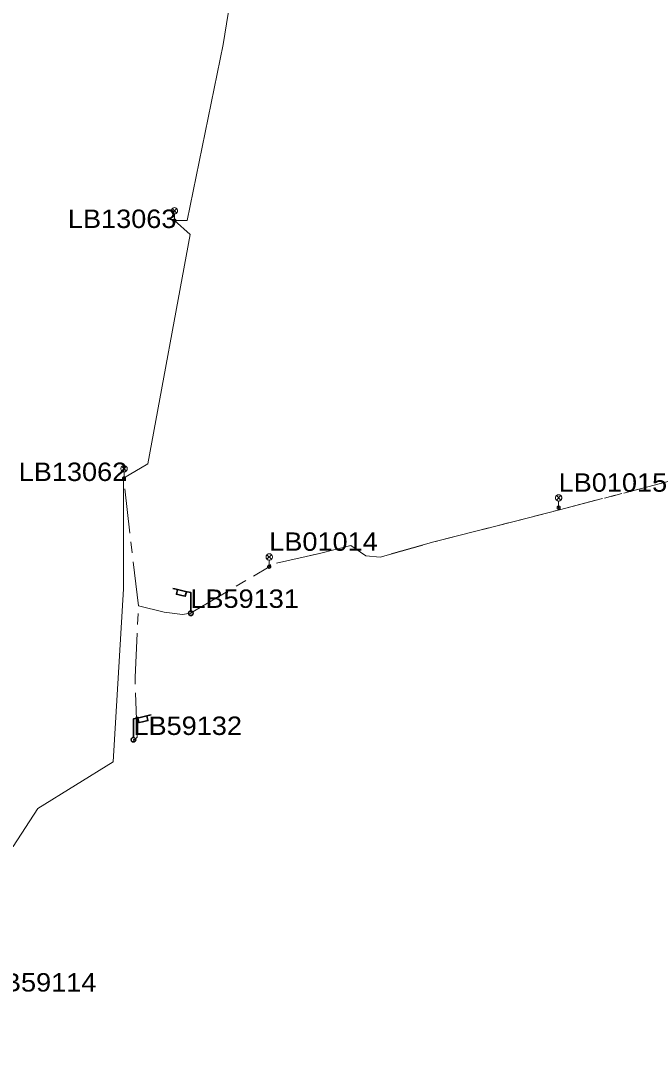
# Model space of a CAD drawing. Extents: x -688049 to -687261, y -973611 to -973038.
# Drawn here: x -687593.4 to -687519.3, y -973304.1 to -973181.4 of the extents above; entities that cross this region are included whole.
import ezdxf

# ---------------------------------------------------------------- set-up
doc = ezdxf.new("R2010")
doc.units = 0
doc.header["$LTSCALE"] = 0.87
doc.linetypes.add('LONG_DASH_SHORT_DASH', pattern=[9.9, 6, -1.2, 1.5, -1.2])
doc.layers.add('1', color=7, linetype='Continuous', lineweight=13)

msp = doc.modelspace()

# ---------------------------------------------------------------- linework, layer by layer
at = {"layer": '1'}
for p, q in [((-687575.645, -973203.485), (-687575.115, -973204.015)), ((-687575.645, -973204.015), (-687575.115, -973203.485)), ((-687575.38, -973204.9), (-687575.38, -973204.125)), ((-687581.575, -973233.825), (-687581.045, -973234.355)), ((-687581.575, -973234.355), (-687581.045, -973233.825)), ((-687581.31, -973235.24), (-687581.31, -973234.465)), ((-687530.455, -973237.255), (-687529.925, -973237.785)), ((-687530.455, -973237.785), (-687529.925, -973237.255)), ((-687530.19, -973238.67), (-687530.19, -973237.895)), ((-687564.495, -973244.205), (-687563.965, -973244.735)), ((-687564.495, -973244.735), (-687563.965, -973244.205)), ((-687564.23, -973245.62), (-687564.23, -973244.845))]:
    msp.add_line(p, q, dxfattribs=at)
at = {"layer": '1', "linetype": 'LONG_DASH_SHORT_DASH'}
for p, q in [((-687579.62, -973250.21), (-687581.366, -973235.196)), ((-687579.62, -973250.21), (-687581.366, -973235.196)), ((-687579.62, -973250.21), (-687581.366, -973235.196)), ((-687579.62, -973250.21), (-687581.366, -973235.196)), ((-687579.62, -973250.21), (-687581.366, -973235.196)), ((-687579.62, -973250.21), (-687581.366, -973235.196)), ((-687579.62, -973250.21), (-687581.366, -973235.196)), ((-687530.07, -973238.91), (-687520.8, -973236.51)), ((-687530.07, -973238.91), (-687520.8, -973236.51)), ((-687530.07, -973238.91), (-687520.8, -973236.51)), ((-687530.07, -973238.91), (-687520.8, -973236.51)), ((-687539.11, -973241.23), (-687530.07, -973238.91)), ((-687539.11, -973241.23), (-687530.07, -973238.91)), ((-687539.11, -973241.23), (-687530.07, -973238.91)), ((-687530.07, -973238.91), (-687530.19, -973238.67)), ((-687530.07, -973238.91), (-687530.19, -973238.67)), ((-687530.07, -973238.91), (-687530.19, -973238.67)), ((-687573.51, -973251.1), (-687564.23, -973245.62)), ((-687573.51, -973251.1), (-687564.23, -973245.62)), ((-687573.51, -973251.1), (-687564.23, -973245.62)), ((-687573.51, -973251.1), (-687564.23, -973245.62)), ((-687573.51, -973251.1), (-687564.23, -973245.62)), ((-687573.51, -973251.1), (-687564.23, -973245.62)), ((-687573.51, -973251.1), (-687564.23, -973245.62)), ((-687580.01, -973258.67), (-687579.62, -973250.21)), ((-687580.01, -973258.67), (-687579.62, -973250.21)), ((-687580.01, -973258.67), (-687579.62, -973250.21)), ((-687580.01, -973258.67), (-687579.62, -973250.21)), ((-687580.01, -973258.67), (-687579.62, -973250.21)), ((-687580.01, -973258.67), (-687579.62, -973250.21)), ((-687579.62, -973250.21), (-687576.58, -973250.95)), ((-687579.62, -973250.21), (-687576.58, -973250.95)), ((-687579.62, -973250.21), (-687576.58, -973250.95)), ((-687579.62, -973250.21), (-687576.58, -973250.95)), ((-687579.62, -973250.21), (-687576.58, -973250.95)), ((-687579.62, -973250.21), (-687576.58, -973250.95)), ((-687579.62, -973250.21), (-687576.58, -973250.95)), ((-687576.58, -973250.95), (-687574.42, -973251.25)), ((-687576.58, -973250.95), (-687574.42, -973251.25)), ((-687576.58, -973250.95), (-687574.42, -973251.25)), ((-687576.58, -973250.95), (-687574.42, -973251.25)), ((-687576.58, -973250.95), (-687574.42, -973251.25)), ((-687576.58, -973250.95), (-687574.42, -973251.25)), ((-687574.42, -973251.25), (-687573.51, -973251.1)), ((-687574.42, -973251.25), (-687573.51, -973251.1)), ((-687574.42, -973251.25), (-687573.51, -973251.1)), ((-687574.42, -973251.25), (-687573.51, -973251.1)), ((-687574.42, -973251.25), (-687573.51, -973251.1)), ((-687574.42, -973251.25), (-687573.51, -973251.1)), ((-687579.78, -973265.69), (-687580.01, -973258.67)), ((-687579.78, -973265.69), (-687580.01, -973258.67)), ((-687579.78, -973265.69), (-687580.01, -973258.67)), ((-687579.78, -973265.69), (-687580.01, -973258.67)), ((-687580.2, -973266.05), (-687579.78, -973265.69)), ((-687580.2, -973266.05), (-687579.78, -973265.69)), ((-687580.2, -973266.05), (-687579.78, -973265.69)), ((-687580.2, -973266.05), (-687579.78, -973265.69)), ((-687580.2, -973266.05), (-687579.78, -973265.69)), ((-687580.2, -973266.05), (-687579.78, -973265.69))]:
    msp.add_line(p, q, dxfattribs=at)
at = {"layer": '1', "lineweight": 35}
for p, q in [((-687573.425, -973251.1), (-687573.479, -973251.1)), ((-687580.243, -973265.968), (-687580.189, -973265.968))]:
    msp.add_line(p, q, dxfattribs=at)
at = {"layer": '1'}
for points in [[(-687575.38, -973204.9), (-687573.874, -973204.9), (-687569.663, -973184.163), (-687567.048, -973168.085), (-687568.06, -973166.7)], [(-687581.366, -973235.196), (-687578.492, -973233.52), (-687573.548, -973206.552), (-687575.38, -973204.9)], [(-687581.366, -973235.196), (-687581.366, -973248.239), (-687582.584, -973268.559), (-687591.459, -973274.079), (-687594.36, -973278.544), (-687605.262, -973276.884), (-687608.072, -973288.54), (-687610.025, -973292.76), (-687612.471, -973294.66), (-687613.949, -973301.72), (-687622.891, -973301.881), (-687623.316, -973303.267), (-687623.86, -973304.14)]]:
    msp.add_lwpolyline(points, dxfattribs=at)
for points in [[(-687575.005, -973203.75), (-687575.011, -973203.685), (-687575.028, -973203.622), (-687575.055, -973203.562), (-687575.093, -973203.509), (-687575.139, -973203.463), (-687575.192, -973203.425), (-687575.252, -973203.398), (-687575.315, -973203.381), (-687575.38, -973203.375), (-687575.445, -973203.381), (-687575.508, -973203.398), (-687575.568, -973203.425), (-687575.621, -973203.463), (-687575.667, -973203.509), (-687575.705, -973203.562), (-687575.732, -973203.622), (-687575.749, -973203.685), (-687575.755, -973203.75), (-687575.749, -973203.815), (-687575.732, -973203.878), (-687575.705, -973203.938), (-687575.667, -973203.991), (-687575.621, -973204.037), (-687575.568, -973204.075), (-687575.508, -973204.102), (-687575.445, -973204.119), (-687575.38, -973204.125), (-687575.315, -973204.119), (-687575.252, -973204.102), (-687575.192, -973204.075), (-687575.139, -973204.037), (-687575.093, -973203.991), (-687575.055, -973203.938), (-687575.028, -973203.878), (-687575.011, -973203.815)], [(-687575.19, -973204.9), (-687575.193, -973204.867), (-687575.201, -973204.835), (-687575.215, -973204.805), (-687575.234, -973204.778), (-687575.258, -973204.754), (-687575.285, -973204.735), (-687575.315, -973204.721), (-687575.347, -973204.713), (-687575.38, -973204.71), (-687575.413, -973204.713), (-687575.445, -973204.721), (-687575.475, -973204.735), (-687575.502, -973204.754), (-687575.526, -973204.778), (-687575.545, -973204.805), (-687575.559, -973204.835), (-687575.567, -973204.867), (-687575.57, -973204.9), (-687575.567, -973204.933), (-687575.559, -973204.965), (-687575.545, -973204.995), (-687575.526, -973205.022), (-687575.502, -973205.046), (-687575.475, -973205.065), (-687575.445, -973205.079), (-687575.413, -973205.087), (-687575.38, -973205.09), (-687575.347, -973205.087), (-687575.315, -973205.079), (-687575.285, -973205.065), (-687575.258, -973205.046), (-687575.234, -973205.022), (-687575.215, -973204.995), (-687575.201, -973204.965), (-687575.193, -973204.933)], [(-687575.33, -973204.9), (-687575.331, -973204.891), (-687575.333, -973204.883), (-687575.337, -973204.875), (-687575.342, -973204.868), (-687575.348, -973204.862), (-687575.355, -973204.857), (-687575.363, -973204.853), (-687575.371, -973204.851), (-687575.38, -973204.85), (-687575.389, -973204.851), (-687575.397, -973204.853), (-687575.405, -973204.857), (-687575.412, -973204.862), (-687575.418, -973204.868), (-687575.423, -973204.875), (-687575.427, -973204.883), (-687575.429, -973204.891), (-687575.43, -973204.9), (-687575.429, -973204.909), (-687575.427, -973204.917), (-687575.423, -973204.925), (-687575.418, -973204.932), (-687575.412, -973204.938), (-687575.405, -973204.943), (-687575.397, -973204.947), (-687575.389, -973204.949), (-687575.38, -973204.95), (-687575.371, -973204.949), (-687575.363, -973204.947), (-687575.355, -973204.943), (-687575.348, -973204.938), (-687575.342, -973204.932), (-687575.337, -973204.925), (-687575.333, -973204.917), (-687575.331, -973204.909)], [(-687580.935, -973234.09), (-687580.941, -973234.025), (-687580.958, -973233.962), (-687580.985, -973233.903), (-687581.023, -973233.849), (-687581.069, -973233.803), (-687581.122, -973233.765), (-687581.182, -973233.738), (-687581.245, -973233.721), (-687581.31, -973233.715), (-687581.375, -973233.721), (-687581.438, -973233.738), (-687581.498, -973233.765), (-687581.551, -973233.803), (-687581.597, -973233.849), (-687581.635, -973233.903), (-687581.662, -973233.962), (-687581.679, -973234.025), (-687581.685, -973234.09), (-687581.679, -973234.155), (-687581.662, -973234.218), (-687581.635, -973234.278), (-687581.597, -973234.331), (-687581.551, -973234.377), (-687581.498, -973234.415), (-687581.438, -973234.442), (-687581.375, -973234.459), (-687581.31, -973234.465), (-687581.245, -973234.459), (-687581.182, -973234.442), (-687581.122, -973234.415), (-687581.069, -973234.377), (-687581.023, -973234.331), (-687580.985, -973234.278), (-687580.958, -973234.218), (-687580.941, -973234.155)], [(-687581.12, -973235.24), (-687581.123, -973235.207), (-687581.131, -973235.175), (-687581.145, -973235.145), (-687581.164, -973235.118), (-687581.188, -973235.094), (-687581.215, -973235.075), (-687581.245, -973235.061), (-687581.277, -973235.053), (-687581.31, -973235.05), (-687581.343, -973235.053), (-687581.375, -973235.061), (-687581.405, -973235.075), (-687581.432, -973235.094), (-687581.456, -973235.118), (-687581.475, -973235.145), (-687581.489, -973235.175), (-687581.497, -973235.207), (-687581.5, -973235.24), (-687581.497, -973235.273), (-687581.489, -973235.305), (-687581.475, -973235.335), (-687581.456, -973235.362), (-687581.432, -973235.386), (-687581.405, -973235.405), (-687581.375, -973235.419), (-687581.343, -973235.427), (-687581.31, -973235.43), (-687581.277, -973235.427), (-687581.245, -973235.419), (-687581.215, -973235.405), (-687581.188, -973235.386), (-687581.164, -973235.362), (-687581.145, -973235.335), (-687581.131, -973235.305), (-687581.123, -973235.273)], [(-687581.26, -973235.24), (-687581.261, -973235.231), (-687581.263, -973235.223), (-687581.267, -973235.215), (-687581.272, -973235.208), (-687581.278, -973235.202), (-687581.285, -973235.197), (-687581.293, -973235.193), (-687581.301, -973235.191), (-687581.31, -973235.19), (-687581.319, -973235.191), (-687581.327, -973235.193), (-687581.335, -973235.197), (-687581.342, -973235.202), (-687581.348, -973235.208), (-687581.353, -973235.215), (-687581.357, -973235.223), (-687581.359, -973235.231), (-687581.36, -973235.24), (-687581.359, -973235.249), (-687581.357, -973235.257), (-687581.353, -973235.265), (-687581.348, -973235.272), (-687581.342, -973235.278), (-687581.335, -973235.283), (-687581.327, -973235.287), (-687581.319, -973235.289), (-687581.31, -973235.29), (-687581.301, -973235.289), (-687581.293, -973235.287), (-687581.285, -973235.283), (-687581.278, -973235.278), (-687581.272, -973235.272), (-687581.267, -973235.265), (-687581.263, -973235.257), (-687581.261, -973235.249)], [(-687529.815, -973237.52), (-687529.821, -973237.455), (-687529.838, -973237.392), (-687529.865, -973237.332), (-687529.903, -973237.279), (-687529.949, -973237.233), (-687530.003, -973237.195), (-687530.062, -973237.168), (-687530.125, -973237.151), (-687530.19, -973237.145), (-687530.255, -973237.151), (-687530.318, -973237.168), (-687530.378, -973237.195), (-687530.431, -973237.233), (-687530.477, -973237.279), (-687530.515, -973237.332), (-687530.542, -973237.392), (-687530.559, -973237.455), (-687530.565, -973237.52), (-687530.559, -973237.585), (-687530.542, -973237.648), (-687530.515, -973237.708), (-687530.477, -973237.761), (-687530.431, -973237.807), (-687530.378, -973237.845), (-687530.318, -973237.872), (-687530.255, -973237.889), (-687530.19, -973237.895), (-687530.125, -973237.889), (-687530.062, -973237.872), (-687530.003, -973237.845), (-687529.949, -973237.807), (-687529.903, -973237.761), (-687529.865, -973237.708), (-687529.838, -973237.648), (-687529.821, -973237.585)], [(-687530, -973238.67), (-687530.003, -973238.637), (-687530.011, -973238.605), (-687530.025, -973238.575), (-687530.044, -973238.548), (-687530.068, -973238.524), (-687530.095, -973238.505), (-687530.125, -973238.491), (-687530.157, -973238.483), (-687530.19, -973238.48), (-687530.223, -973238.483), (-687530.255, -973238.491), (-687530.285, -973238.505), (-687530.312, -973238.524), (-687530.336, -973238.548), (-687530.355, -973238.575), (-687530.369, -973238.605), (-687530.377, -973238.637), (-687530.38, -973238.67), (-687530.377, -973238.703), (-687530.369, -973238.735), (-687530.355, -973238.765), (-687530.336, -973238.792), (-687530.312, -973238.816), (-687530.285, -973238.835), (-687530.255, -973238.849), (-687530.223, -973238.857), (-687530.19, -973238.86), (-687530.157, -973238.857), (-687530.125, -973238.849), (-687530.095, -973238.835), (-687530.068, -973238.816), (-687530.044, -973238.792), (-687530.025, -973238.765), (-687530.011, -973238.735), (-687530.003, -973238.703)], [(-687530.14, -973238.67), (-687530.141, -973238.661), (-687530.143, -973238.653), (-687530.147, -973238.645), (-687530.152, -973238.638), (-687530.158, -973238.632), (-687530.165, -973238.627), (-687530.173, -973238.623), (-687530.181, -973238.621), (-687530.19, -973238.62), (-687530.199, -973238.621), (-687530.207, -973238.623), (-687530.215, -973238.627), (-687530.222, -973238.632), (-687530.228, -973238.638), (-687530.233, -973238.645), (-687530.237, -973238.653), (-687530.239, -973238.661), (-687530.24, -973238.67), (-687530.239, -973238.679), (-687530.237, -973238.687), (-687530.233, -973238.695), (-687530.228, -973238.702), (-687530.222, -973238.708), (-687530.215, -973238.713), (-687530.207, -973238.717), (-687530.199, -973238.719), (-687530.19, -973238.72), (-687530.181, -973238.719), (-687530.173, -973238.717), (-687530.165, -973238.713), (-687530.158, -973238.708), (-687530.152, -973238.702), (-687530.147, -973238.695), (-687530.143, -973238.687), (-687530.141, -973238.679)], [(-687563.855, -973244.47), (-687563.861, -973244.405), (-687563.878, -973244.342), (-687563.905, -973244.283), (-687563.943, -973244.229), (-687563.989, -973244.183), (-687564.042, -973244.145), (-687564.102, -973244.118), (-687564.165, -973244.101), (-687564.23, -973244.095), (-687564.295, -973244.101), (-687564.358, -973244.118), (-687564.418, -973244.145), (-687564.471, -973244.183), (-687564.517, -973244.229), (-687564.555, -973244.283), (-687564.582, -973244.342), (-687564.599, -973244.405), (-687564.605, -973244.47), (-687564.599, -973244.535), (-687564.582, -973244.598), (-687564.555, -973244.658), (-687564.517, -973244.711), (-687564.471, -973244.757), (-687564.418, -973244.795), (-687564.358, -973244.822), (-687564.295, -973244.839), (-687564.23, -973244.845), (-687564.165, -973244.839), (-687564.102, -973244.822), (-687564.042, -973244.795), (-687563.989, -973244.757), (-687563.943, -973244.711), (-687563.905, -973244.658), (-687563.878, -973244.598), (-687563.861, -973244.535)], [(-687564.04, -973245.62), (-687564.043, -973245.587), (-687564.051, -973245.555), (-687564.065, -973245.525), (-687564.084, -973245.498), (-687564.108, -973245.474), (-687564.135, -973245.455), (-687564.165, -973245.441), (-687564.197, -973245.433), (-687564.23, -973245.43), (-687564.263, -973245.433), (-687564.295, -973245.441), (-687564.325, -973245.455), (-687564.352, -973245.474), (-687564.376, -973245.498), (-687564.395, -973245.525), (-687564.409, -973245.555), (-687564.417, -973245.587), (-687564.42, -973245.62), (-687564.417, -973245.653), (-687564.409, -973245.685), (-687564.395, -973245.715), (-687564.376, -973245.742), (-687564.352, -973245.766), (-687564.325, -973245.785), (-687564.295, -973245.799), (-687564.263, -973245.807), (-687564.23, -973245.81), (-687564.197, -973245.807), (-687564.165, -973245.799), (-687564.135, -973245.785), (-687564.108, -973245.766), (-687564.084, -973245.742), (-687564.065, -973245.715), (-687564.051, -973245.685), (-687564.043, -973245.653)], [(-687564.18, -973245.62), (-687564.181, -973245.611), (-687564.183, -973245.603), (-687564.187, -973245.595), (-687564.192, -973245.588), (-687564.198, -973245.582), (-687564.205, -973245.577), (-687564.213, -973245.573), (-687564.221, -973245.571), (-687564.23, -973245.57), (-687564.239, -973245.571), (-687564.247, -973245.573), (-687564.255, -973245.577), (-687564.262, -973245.582), (-687564.268, -973245.588), (-687564.273, -973245.595), (-687564.277, -973245.603), (-687564.279, -973245.611), (-687564.28, -973245.62), (-687564.279, -973245.629), (-687564.277, -973245.637), (-687564.273, -973245.645), (-687564.268, -973245.652), (-687564.262, -973245.658), (-687564.255, -973245.663), (-687564.247, -973245.667), (-687564.239, -973245.669), (-687564.23, -973245.67), (-687564.221, -973245.669), (-687564.213, -973245.667), (-687564.205, -973245.663), (-687564.198, -973245.658), (-687564.192, -973245.652), (-687564.187, -973245.645), (-687564.183, -973245.637), (-687564.181, -973245.629)]]:
    msp.add_lwpolyline(points, close=True, dxfattribs=at)
at = {"layer": '1', "linetype": 'LONG_DASH_SHORT_DASH'}
for points in [[(-687494.49, -973230.53), (-687505.37, -973233.46), (-687507.43, -973233.77), (-687511.98, -973233.97), (-687514.17, -973234.4), (-687517.46, -973235.64), (-687530.07, -973238.91)], [(-687494.49, -973230.53), (-687505.37, -973233.46), (-687507.43, -973233.77), (-687511.98, -973233.97), (-687514.17, -973234.4), (-687517.46, -973235.64), (-687530.07, -973238.91)], [(-687494.49, -973230.53), (-687505.37, -973233.46), (-687507.43, -973233.77), (-687511.98, -973233.97), (-687514.17, -973234.4), (-687517.46, -973235.64), (-687530.07, -973238.91)], [(-687494.49, -973230.53), (-687505.37, -973233.46), (-687507.43, -973233.77), (-687511.98, -973233.97), (-687514.17, -973234.4), (-687517.46, -973235.64), (-687530.07, -973238.91)], [(-687579.78, -973265.69), (-687580.01, -973258.67), (-687579.62, -973250.21), (-687581.366, -973235.196)], [(-687580.01, -973258.67), (-687579.62, -973250.21), (-687581.366, -973235.196)], [(-687530.07, -973238.91), (-687544.87, -973242.71), (-687551.18, -973244.48), (-687552.88, -973244.34), (-687554.64, -973243.14), (-687558.3, -973244.05), (-687564.07, -973245.34), (-687564.23, -973245.62)], [(-687530.07, -973238.91), (-687544.87, -973242.71), (-687551.18, -973244.48), (-687552.88, -973244.34), (-687554.64, -973243.14), (-687558.3, -973244.05), (-687564.07, -973245.34), (-687564.07, -973245.71)], [(-687530.07, -973238.91), (-687544.87, -973242.71), (-687551.18, -973244.48), (-687552.88, -973244.34), (-687554.64, -973243.14), (-687558.3, -973244.05), (-687564.07, -973245.34), (-687564.07, -973245.71)], [(-687530.07, -973238.91), (-687544.87, -973242.71), (-687551.18, -973244.48), (-687552.88, -973244.34), (-687554.64, -973243.14), (-687558.3, -973244.05), (-687564.07, -973245.34), (-687564.07, -973245.71)], [(-687539.11, -973241.23), (-687530.07, -973238.91), (-687530.19, -973238.67)], [(-687559.42, -973244.3), (-687558.3, -973244.05), (-687554.64, -973243.14), (-687552.88, -973244.34), (-687551.18, -973244.48), (-687544.87, -973242.71), (-687542.23, -973242.03)], [(-687559.42, -973244.3), (-687558.3, -973244.05), (-687554.64, -973243.14), (-687552.88, -973244.34), (-687551.18, -973244.48), (-687544.87, -973242.71), (-687542.23, -973242.03)], [(-687559.42, -973244.3), (-687558.3, -973244.05), (-687554.64, -973243.14), (-687552.88, -973244.34), (-687551.18, -973244.48), (-687544.87, -973242.71), (-687542.23, -973242.03)], [(-687559.42, -973244.3), (-687558.3, -973244.05), (-687554.64, -973243.14), (-687552.88, -973244.34), (-687551.18, -973244.48), (-687544.87, -973242.71), (-687542.23, -973242.03)], [(-687574.42, -973251.25), (-687573.51, -973251.1), (-687564.23, -973245.62)], [(-687574.42, -973251.25), (-687573.51, -973251.1), (-687564.23, -973245.62)], [(-687579.78, -973265.69), (-687580.01, -973258.67), (-687579.62, -973250.21)], [(-687579.62, -973250.21), (-687576.58, -973250.95), (-687574.42, -973251.25)], [(-687579.62, -973250.21), (-687576.58, -973250.95), (-687574.42, -973251.25)], [(-687576.58, -973250.95), (-687574.42, -973251.25), (-687573.51, -973251.1)], [(-687580.2, -973266.05), (-687579.78, -973265.69), (-687580.01, -973258.67)], [(-687580.2, -973266.05), (-687579.78, -973265.69), (-687580.01, -973258.67)], [(-687580.2, -973266.05), (-687579.78, -973265.69), (-687580.01, -973258.67)]]:
    msp.add_lwpolyline(points, dxfattribs=at)
at = {"layer": '1', "lineweight": 35}
for points in [[(-687573.452, -973250.845), (-687573.539, -973250.845), (-687573.674, -973250.943), (-687573.728, -973251.1), (-687573.674, -973251.257), (-687573.539, -973251.355), (-687573.371, -973251.355), (-687573.235, -973251.257), (-687573.181, -973251.1), (-687573.235, -973250.943), (-687573.371, -973250.845), (-687573.452, -973250.845), (-687573.452, -973250.157), (-687573.452, -973249.469), (-687573.452, -973248.781), (-687573.452, -973248.662), (-687574.086, -973248.515), (-687574.72, -973248.369), (-687575.354, -973248.223), (-687575.565, -973248.174)], [(-687575.023, -973248.309), (-687575.159, -973248.851), (-687574.525, -973248.998), (-687574.102, -973249.095), (-687573.967, -973248.553)], [(-687580.216, -973265.713), (-687580.129, -973265.713), (-687579.994, -973265.811), (-687579.94, -973265.968), (-687579.994, -973266.125), (-687580.129, -973266.223), (-687580.297, -973266.223), (-687580.433, -973266.125), (-687580.487, -973265.968), (-687580.433, -973265.811), (-687580.297, -973265.713), (-687580.216, -973265.713), (-687580.216, -973265.025), (-687580.216, -973264.337), (-687580.216, -973263.649), (-687580.216, -973263.53), (-687579.582, -973263.383), (-687578.948, -973263.237), (-687578.314, -973263.091), (-687578.103, -973263.042)], [(-687578.645, -973263.177), (-687578.509, -973263.719), (-687579.143, -973263.866), (-687579.566, -973263.963), (-687579.701, -973263.421)]]:
    msp.add_lwpolyline(points, dxfattribs=at)

# ---------------------------------------------------------------- texts
at = {"layer": '1', "width": 1.1}
for s, p in [('LB13063', (-687587.912, -973205.768)), ('LB13062', (-687593.699, -973235.533)), ('LB01015', (-687530.19, -973236.797)), ('LB01014', (-687564.23, -973243.747)), ('LB59131', (-687573.51, -973250.462)), ('LB59132', (-687580.2, -973265.412)), ('LB59114', (-687597.328, -973295.603))]:
    msp.add_text(s, height=2.167, dxfattribs=at).set_placement(p)

doc.saveas('drawing.dxf')
